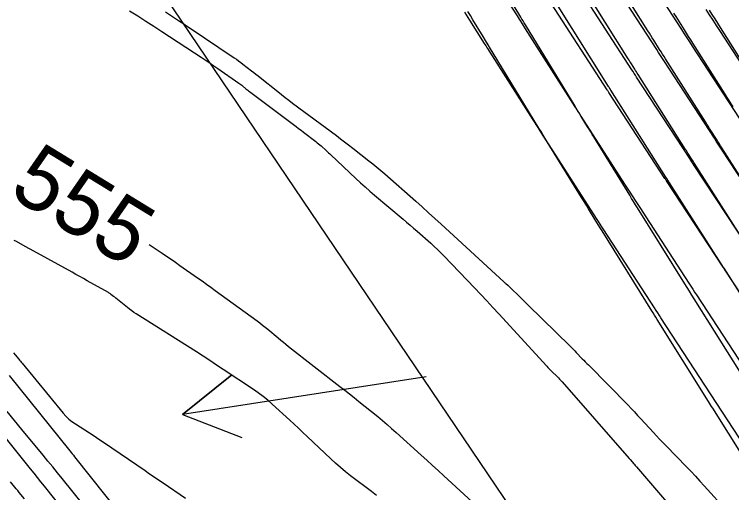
# Model space of a CAD drawing. Extents: x 954385 to 988206, y 1868364 to 1924553.
# Drawn here: x 957618.2 to 957686, y 1920108 to 1920153.2 of the extents above; entities that cross this region are included whole.
import ezdxf

# ---------------------------------------------------------------- set-up
doc = ezdxf.new("R2010")
doc.units = 0
for name, color, linetype in [('1', 7, 'Continuous'), ('Default', 7, 'Continuous'), ('Ex_Contour Labels', 7, 'Continuous'), ('Ex_Major Contours', 7, 'Continuous'), ('Ex_Minor Contours', 7, 'Continuous'), ('Slopes', 7, 'Continuous')]:
    doc.layers.add(name, color=color, linetype=linetype)

msp = doc.modelspace()

# ---------------------------------------------------------------- linework, layer by layer
at = {"layer": '1'}
for points in [[(957676.664, 1920158.926), (957681.289, 1920151.772), (957681.542, 1920151.38), (957681.797, 1920150.988), (957682.051, 1920150.596), (957682.306, 1920150.205), (957686.746, 1920143.39)], [(957689.891, 1920133.126), (957685.137, 1920140.369), (957684.954, 1920140.648), (957684.771, 1920140.927), (957684.588, 1920141.206), (957684.406, 1920141.486), (957679.678, 1920148.744), (957679.495, 1920149.025), (957679.311, 1920149.307), (957679.129, 1920149.589), (957678.946, 1920149.871), (957674.227, 1920157.171)], [(957664.337, 1920155.283), (957665.737, 1920153.07), (957665.93, 1920152.764), (957666.123, 1920152.459), (957666.317, 1920152.154), (957666.511, 1920151.849), (957671.213, 1920144.464), (957671.354, 1920144.242), (957671.496, 1920144.02), (957671.638, 1920143.799), (957671.78, 1920143.577), (957675.911, 1920137.156), (957676.409, 1920136.382), (957676.909, 1920135.609), (957677.409, 1920134.836), (957677.911, 1920134.064), (957681.999, 1920127.774), (957682.178, 1920127.498), (957682.358, 1920127.222), (957682.538, 1920126.946), (957682.718, 1920126.67), (957717.191, 1920073.906)], [(957687.556, 1920131.218), (957682.506, 1920138.911), (957682.396, 1920139.078), (957682.286, 1920139.246), (957682.176, 1920139.414), (957682.067, 1920139.582), (957677.05, 1920147.282), (957676.938, 1920147.454), (957676.826, 1920147.626), (957676.715, 1920147.798), (957676.603, 1920147.97), (957671.624, 1920155.673)], [(957720.645, 1920075.559), (957685.358, 1920129.1), (957685.324, 1920129.152), (957685.289, 1920129.205), (957685.255, 1920129.257), (957685.22, 1920129.31), (957679.875, 1920137.452), (957679.838, 1920137.509), (957679.801, 1920137.565), (957679.764, 1920137.622), (957679.727, 1920137.678), (957674.422, 1920145.821), (957674.382, 1920145.883), (957674.341, 1920145.945), (957674.301, 1920146.007), (957674.261, 1920146.069), (957668.999, 1920154.208)], [(957629.068, 1920153.539), (957629.84, 1920153.06), (957630.608, 1920152.576), (957631.373, 1920152.086), (957632.134, 1920151.591), (957635.953, 1920149.09), (957636.322, 1920148.847), (957636.69, 1920148.601), (957637.056, 1920148.353), (957637.42, 1920148.102), (957639.426, 1920146.712), (957639.513, 1920146.651), (957639.597, 1920146.587), (957639.68, 1920146.522), (957639.762, 1920146.454), (957640.084, 1920146.179), (957640.165, 1920146.111), (957640.247, 1920146.044), (957640.33, 1920145.979), (957640.414, 1920145.915), (957644.591, 1920142.787), (957644.829, 1920142.609), (957645.067, 1920142.429), (957645.304, 1920142.249), (957645.54, 1920142.067), (957646.705, 1920141.171), (957646.829, 1920141.073), (957646.952, 1920140.973), (957647.072, 1920140.87), (957647.19, 1920140.765), (957647.658, 1920140.34), (957647.775, 1920140.233), (957647.891, 1920140.126), (957648.007, 1920140.018), (957648.122, 1920139.91), (957650.483, 1920137.683), (957650.918, 1920137.279), (957651.358, 1920136.882), (957651.804, 1920136.49), (957652.256, 1920136.105), (957654.955, 1920133.841), (957655.287, 1920133.56), (957655.617, 1920133.278), (957655.945, 1920132.993), (957656.272, 1920132.707), (957657.575, 1920131.556), (957657.897, 1920131.265), (957658.214, 1920130.968), (957658.524, 1920130.664), (957658.828, 1920130.354), (957661.721, 1920127.338), (957662.302, 1920126.729), (957662.879, 1920126.117), (957663.452, 1920125.501), (957664.021, 1920124.881), (957668.536, 1920119.936), (957668.655, 1920119.808), (957668.775, 1920119.682), (957668.897, 1920119.558), (957669.02, 1920119.435), (957669.518, 1920118.949), (957669.642, 1920118.826), (957669.763, 1920118.701), (957669.881, 1920118.574), (957669.997, 1920118.444), (957676.341, 1920111.214), (957676.348, 1920111.205), (957676.356, 1920111.197), (957676.364, 1920111.189), (957676.372, 1920111.18), (957676.403, 1920111.148), (957676.411, 1920111.14), (957676.419, 1920111.132), (957676.426, 1920111.123), (957676.434, 1920111.115), (957676.794, 1920110.699), (957676.856, 1920110.627), (957676.918, 1920110.555), (957676.981, 1920110.483), (957677.043, 1920110.41), (957687.555, 1920098.121)], [(957714.14, 1920071.263), (957679.353, 1920124.508), (957679.199, 1920124.744), (957679.045, 1920124.981), (957678.891, 1920125.218), (957678.737, 1920125.454), (957673.931, 1920132.847), (957673.763, 1920133.107), (957673.594, 1920133.367), (957673.426, 1920133.627), (957673.259, 1920133.888), (957669.121, 1920140.32), (957668.652, 1920141.05), (957668.184, 1920141.78), (957667.717, 1920142.511), (957667.25, 1920143.242), (957662.96, 1920149.981), (957662.885, 1920150.099), (957662.81, 1920150.218), (957662.735, 1920150.336), (957662.66, 1920150.455), (957661.26, 1920152.668), (957661.102, 1920152.919), (957660.944, 1920153.169), (957660.786, 1920153.42)], [(957689.085, 1920145.294), (957684.934, 1920151.666), (957684.608, 1920152.167), (957684.282, 1920152.669), (957683.956, 1920153.171), (957683.631, 1920153.673)], [(957652.448, 1920107.695), (957651.962, 1920108.077), (957649.987, 1920109.573), (957649.5, 1920109.953), (957649.023, 1920110.347), (957648.558, 1920110.755), (957648.104, 1920111.175), (957645.885, 1920113.293), (957645.475, 1920113.681), (957645.064, 1920114.067), (957644.65, 1920114.45), (957644.234, 1920114.83), (957642.564, 1920116.348), (957642.14, 1920116.719), (957641.703, 1920117.073), (957641.253, 1920117.411), (957640.79, 1920117.731), (957637.94, 1920119.628), (957637.307, 1920120.046), (957636.672, 1920120.461), (957636.035, 1920120.872), (957635.395, 1920121.28), (957629.699, 1920124.884), (957629.485, 1920125.024), (957629.275, 1920125.171), (957629.069, 1920125.323), (957628.867, 1920125.481), (957627.788, 1920126.355), (957627.729, 1920126.402), (957627.671, 1920126.449), (957627.612, 1920126.496), (957627.553, 1920126.542), (957627.316, 1920126.727), (957627.256, 1920126.772), (957627.195, 1920126.814), (957627.132, 1920126.855), (957627.067, 1920126.893), (957625.069, 1920128.022), (957624.714, 1920128.222), (957624.359, 1920128.421), (957624.003, 1920128.619), (957623.646, 1920128.816), (957620.011, 1920130.815), (957619.187, 1920131.268), (957618.363, 1920131.721), (957618.157, 1920131.834)], [(957617.694, 1920119.048), (957623.424, 1920111.927), (957623.534, 1920111.79), (957623.644, 1920111.652), (957623.754, 1920111.515), (957623.863, 1920111.378), (957629.789, 1920103.942)], [(957614.235, 1920116.987), (957619.679, 1920110.221), (957620.005, 1920109.816), (957620.33, 1920109.411), (957620.654, 1920109.005), (957620.979, 1920108.599), (957625.894, 1920102.431)]]:
    msp.add_lwpolyline(points, dxfattribs=at)
at = {"layer": 'Default'}
msp.add_line((957696.959, 1920059.51), (957504.115, 1920344.606), dxfattribs=at)
at = {"layer": 'Ex_Major Contours'}
for points in [[(957686.862, 1920119.332), (957682.492, 1920126.316), (957682.273, 1920126.666), (957682.054, 1920127.016), (957681.835, 1920127.367), (957681.617, 1920127.717), (957677.135, 1920134.911), (957676.948, 1920135.211), (957676.763, 1920135.51), (957676.577, 1920135.81), (957676.392, 1920136.11), (957673.004, 1920141.612), (957672.855, 1920141.854), (957672.706, 1920142.096), (957672.557, 1920142.338), (957672.408, 1920142.58), (957671.812, 1920143.548), (957671.663, 1920143.79), (957671.515, 1920144.033), (957671.366, 1920144.275), (957671.218, 1920144.518), (957666.518, 1920152.226), (957666.41, 1920152.403), (957666.303, 1920152.58), (957666.195, 1920152.758), (957666.088, 1920152.935), (957661.759, 1920160.111)], [(957683.915, 1920153.591), (957684.173, 1920153.18), (957684.431, 1920152.77), (957684.69, 1920152.36), (957684.949, 1920151.95), (957687.288, 1920148.262)], [(957630.931, 1920131.45), (957632.157, 1920130.627), (957632.58, 1920130.341), (957633.001, 1920130.052), (957633.421, 1920129.761), (957633.84, 1920129.468), (957635.51, 1920128.291), (957635.927, 1920127.996), (957636.343, 1920127.699), (957636.758, 1920127.401), (957637.171, 1920127.101), (957641.143, 1920124.214), (957641.399, 1920124.024), (957641.652, 1920123.83), (957641.902, 1920123.632), (957642.149, 1920123.429), (957643.129, 1920122.611), (957643.375, 1920122.408), (957643.622, 1920122.207), (957643.872, 1920122.007), (957644.123, 1920121.81), (957648.978, 1920118.031), (957649.429, 1920117.678), (957649.879, 1920117.323), (957650.327, 1920116.966), (957650.773, 1920116.607), (957652.556, 1920115.167), (957652.999, 1920114.803), (957653.437, 1920114.434), (957653.869, 1920114.058), (957654.297, 1920113.676), (957656.66, 1920111.534), (957657.194, 1920111.048), (957657.728, 1920110.561), (957658.261, 1920110.072), (957658.793, 1920109.583), (957663.778, 1920104.987)]]:
    msp.add_lwpolyline(points, dxfattribs=at)
at = {"layer": 'Ex_Minor Contours'}
for points in [[(957689.009, 1920134.478), (957685.115, 1920140.572), (957684.984, 1920140.778), (957684.853, 1920140.983), (957684.723, 1920141.189), (957684.593, 1920141.394), (957684.073, 1920142.218), (957683.943, 1920142.424), (957683.813, 1920142.629), (957683.682, 1920142.835), (957683.552, 1920143.041), (957679.777, 1920148.995), (957679.638, 1920149.214), (957679.499, 1920149.434), (957679.361, 1920149.654), (957679.222, 1920149.874), (957678.67, 1920150.754), (957678.532, 1920150.974), (957678.394, 1920151.194), (957678.256, 1920151.414), (957678.118, 1920151.634), (957674.468, 1920157.434)], [(957687.14, 1920131.879), (957682.53, 1920139.093), (957682.46, 1920139.205), (957682.389, 1920139.316), (957682.318, 1920139.427), (957682.248, 1920139.539), (957681.966, 1920139.985), (957681.896, 1920140.096), (957681.825, 1920140.207), (957681.755, 1920140.319), (957681.684, 1920140.43), (957677.19, 1920147.517), (957677.112, 1920147.642), (957677.033, 1920147.766), (957676.955, 1920147.891), (957676.876, 1920148.015), (957676.564, 1920148.514), (957676.485, 1920148.639), (957676.407, 1920148.763), (957676.329, 1920148.888), (957676.25, 1920149.013), (957671.88, 1920155.958)], [(957688.086, 1920124.893), (957685.317, 1920129.207), (957685.302, 1920129.231), (957685.27, 1920129.281), (957679.946, 1920137.615), (957679.924, 1920137.649), (957679.902, 1920137.683), (957679.849, 1920137.768), (957679.816, 1920137.82), (957674.604, 1920146.04), (957674.586, 1920146.069), (957674.567, 1920146.098), (957674.549, 1920146.127), (957674.53, 1920146.157), (957674.438, 1920146.303), (957674.402, 1920146.362), (957674.383, 1920146.391), (957669.293, 1920154.481)], [(957632.479, 1920153.444), (957633.692, 1920152.634), (957633.944, 1920152.466), (957634.196, 1920152.298), (957634.448, 1920152.129), (957634.701, 1920151.961), (957638.963, 1920149.111), (957639.177, 1920148.965), (957639.388, 1920148.816), (957639.597, 1920148.664), (957639.803, 1920148.508), (957640.624, 1920147.877), (957640.829, 1920147.719), (957641.033, 1920147.559), (957641.236, 1920147.399), (957641.438, 1920147.238), (957643.104, 1920145.901), (957643.45, 1920145.626), (957643.799, 1920145.354), (957644.15, 1920145.085), (957644.503, 1920144.819), (957648.638, 1920141.739), (957649.027, 1920141.448), (957649.414, 1920141.155), (957649.799, 1920140.86), (957650.183, 1920140.563), (957651.715, 1920139.37), (957652.096, 1920139.068), (957652.472, 1920138.762), (957652.843, 1920138.449), (957653.209, 1920138.13), (957656.142, 1920135.538), (957656.751, 1920134.998), (957657.357, 1920134.454), (957657.96, 1920133.908), (957658.561, 1920133.358), (957664.499, 1920127.899), (957664.542, 1920127.86), (957664.586, 1920127.82), (957664.63, 1920127.782), (957664.675, 1920127.743), (957664.853, 1920127.591), (957664.898, 1920127.552), (957664.941, 1920127.513), (957664.984, 1920127.473), (957665.027, 1920127.433), (957666.058, 1920126.426), (957666.429, 1920126.063), (957666.801, 1920125.7), (957670.763, 1920121.832), (957670.909, 1920121.687), (957671.055, 1920121.541), (957671.199, 1920121.393), (957671.341, 1920121.244), (957671.907, 1920120.644), (957672.049, 1920120.495), (957672.192, 1920120.346), (957672.335, 1920120.198), (957672.48, 1920120.051), (957676.234, 1920116.236), (957676.54, 1920115.922), (957676.844, 1920115.606), (957677.145, 1920115.287), (957677.443, 1920114.966), (957678.629, 1920113.674), (957678.927, 1920113.352), (957679.227, 1920113.033), (957679.53, 1920112.716), (957679.835, 1920112.401), (957681.778, 1920110.408), (957682.201, 1920109.969), (957682.621, 1920109.527), (957683.037, 1920109.08), (957683.448, 1920108.63), (957685.61, 1920106.243)], [(957688.693, 1920108.877), (957684.243, 1920115.982), (957684.146, 1920116.137), (957684.049, 1920116.292), (957683.951, 1920116.448), (957683.854, 1920116.603), (957678.997, 1920124.364), (957678.869, 1920124.57), (957678.741, 1920124.775), (957678.612, 1920124.981), (957678.484, 1920125.186), (957673.773, 1920132.749), (957673.611, 1920133.009), (957673.45, 1920133.269), (957673.289, 1920133.529), (957673.128, 1920133.79), (957672.486, 1920134.832), (957672.326, 1920135.093), (957672.165, 1920135.353), (957672.005, 1920135.614), (957671.845, 1920135.874), (957668.598, 1920141.146), (957668.4, 1920141.469), (957668.201, 1920141.792), (957668.004, 1920142.115), (957667.806, 1920142.439), (957663.468, 1920149.552), (957663.229, 1920149.946), (957662.99, 1920150.339), (957662.751, 1920150.733), (957662.513, 1920151.127), (957661.561, 1920152.705), (957661.324, 1920153.099), (957661.086, 1920153.493)], [(957686.18, 1920144.451), (957685.99, 1920144.751), (957685.8, 1920145.051), (957685.61, 1920145.351), (957685.42, 1920145.651), (957682.363, 1920150.472), (957682.164, 1920150.787), (957681.965, 1920151.102), (957681.767, 1920151.417), (957681.569, 1920151.733), (957680.777, 1920152.995), (957680.579, 1920153.31)], [(957618.091, 1920121.204), (957618.255, 1920121.007), (957618.583, 1920120.611), (957618.665, 1920120.512), (957618.747, 1920120.413), (957618.829, 1920120.314), (957618.91, 1920120.215), (957622.778, 1920115.502), (957623.039, 1920115.209), (957623.321, 1920114.94), (957623.623, 1920114.694), (957623.947, 1920114.472), (957625.283, 1920113.633), (957625.616, 1920113.421), (957625.946, 1920113.206), (957626.275, 1920112.988), (957626.601, 1920112.766), (957630.54, 1920110.063), (957630.968, 1920109.769), (957631.397, 1920109.477), (957631.826, 1920109.185), (957632.256, 1920108.894), (957634.364, 1920107.471)], [(957624.785, 1920106.747), (957622.703, 1920109.306), (957622.254, 1920109.857), (957621.804, 1920110.408), (957621.354, 1920110.959), (957620.903, 1920111.509), (957618.887, 1920113.965), (957618.196, 1920114.807), (957617.505, 1920115.648)], [(957619.118, 1920107.399), (957618.63, 1920107.998), (957618.561, 1920108.083), (957618.492, 1920108.168), (957618.423, 1920108.253), (957618.353, 1920108.337), (957617.798, 1920109.014)]]:
    msp.add_lwpolyline(points, dxfattribs=at)
at = {"layer": 'Slopes'}
msp.add_lwpolyline([(957657.131, 1920118.928), (957634.087, 1920115.365), (957638.764, 1920119.124), (957634.087, 1920115.365), (957639.681, 1920113.194)], dxfattribs=at)

# ---------------------------------------------------------------- texts
at = {"layer": 'Ex_Contour Labels'}
msp.add_text('555', height=6, rotation=328.51858, dxfattribs=at).set_placement((957617.486, 1920136.166))

doc.saveas('drawing.dxf')
